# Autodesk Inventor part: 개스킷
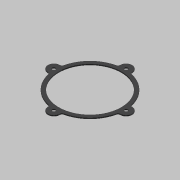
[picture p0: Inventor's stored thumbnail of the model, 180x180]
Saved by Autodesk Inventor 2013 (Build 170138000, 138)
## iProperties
Created: 2018-05
Part Number: 개스킷
Material: 고무, 실리콘
Document SubType Name: Modeling
Designer: mduedu
Density: 1.25 g/cm^3
Mass: 3.80543 g
Surface Area: 51.2947 cm^2
Volume: 3.04434 cm^3
Author: mduedu
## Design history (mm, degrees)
sketch "스케치1"
  geometry: C1 r 45 at (0, 0); C2 r 50 at (0, 0); 1 further point
  constraints: 2 centre point, 1 coincident, 1 concentric
  dimensions: "d12" = 90 diameter of C1; "d14" = 100 diameter of C2
extrude "돌출1" new body sketch "스케치1" distance "d10" = 1.5; taper "d11" = 0 deg
sketch "스케치2"
  geometry: C1 r 50 at (0, 0) reference; A1 r 8.5 centre (0, 52) between (8.074, 49.344) and (-8.074, 49.344); A2 r 50 centre (0, 0) between (-8.074, 49.344) and (8.074, 49.344); A3 r 8.5 centre (0, 52) between (-8.074, 49.344) and (8.074, 49.344); 1 further point
  constraints: 6 point on circle, 3 centre point, 1 concentric, 1 vertical alignment
  dimensions: "d15" = 52 distance of A1.centre point (0, 0); "d16" = 8.5 radius of A1; "d17" = 100 diameter of A2
extrude "돌출2" join sketch "스케치2" stored distance "d18" = 10; taper "d19" = 0 deg
sketch "스케치3"
  geometry: C1 r 2.5 at (0, 52); A1 r 8.5 centre (0, 52) between (8.074, 49.344) and (-8.074, 49.344) reference; 1 further point
  constraints: 1 centre point, 1 concentric
  dimensions: "d20" = 5 diameter of C1
extrude "돌출3" cut sketch "스케치3" stored distance "d21" = 10; taper "d22" = 0 deg
fillet "모깎기1" dims "d23" = 3
node "솔리드1"
pattern_circular "원형 패턴1" dims "d25" = 360 deg
